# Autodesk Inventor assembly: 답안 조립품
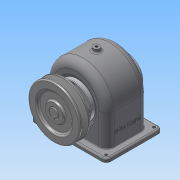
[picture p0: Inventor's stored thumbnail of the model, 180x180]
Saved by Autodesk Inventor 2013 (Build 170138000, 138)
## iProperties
Created: 2016-01
Part Number: 답안 조립품
Document SubType Name: Assembly
Designer: Administrator
Author: Administrator
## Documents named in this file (16)
- C:\Users\Administrator\Desktop\460106V1034\답안 조립품.iam
- C:\Users\Administrator\Desktop\460106V1034\답안 본체.ipt
- C:\Users\Administrator\Desktop\460106V1034\뒤커버.ipt
- C:\Users\Administrator\Desktop\460106V1034\볼트 M3 x 8.ipt
- C:\Users\Administrator\Desktop\460106V1034\베어링 6203.ipt
- C:\Users\Administrator\Desktop\460106V1034\앞커버.ipt
- C:\Users\Administrator\Desktop\460106V1034\볼트 M3 x 10.ipt
- C:\Users\Administrator\Desktop\460106V1034\오일씰 28 40 8.ipt
- C:\Users\Administrator\Desktop\460106V1034\축.ipt
- C:\Users\Administrator\Desktop\460106V1034\키 - 6 x 6 x 22.ipt
- C:\Users\Administrator\Desktop\460106V1034\키 - 5 x 5 x 18.ipt
- C:\Users\Administrator\Desktop\460106V1034\부시2.ipt
- C:\Users\Administrator\Desktop\460106V1034\부시1.ipt
- C:\Users\Administrator\Desktop\460106V1034\V-벨트풀리.ipt
- C:\Users\Administrator\Desktop\460106V1034\멈춤나사 - M4x10.ipt
- C:\Users\Administrator\Desktop\460106V1034\스퍼기어.ipt
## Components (9 placed, 3 different names)
1. V-벨트풀리:1 — 각도:3
2. ISO 4762 M3 x 8:1
3. ISO 4762 M3 x 8:2
4. ISO 4762 M3 x 8:3
5. ISO 4762 M3 x 8:4
6. ISO 4762 M3 x 10:1
7. ISO 4762 M3 x 10:2
8. ISO 4762 M3 x 10:3
9. ISO 4762 M3 x 10:4
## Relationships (1: Angle 1)
- 각도:3 [Angle]: V-벨트풀리:1
